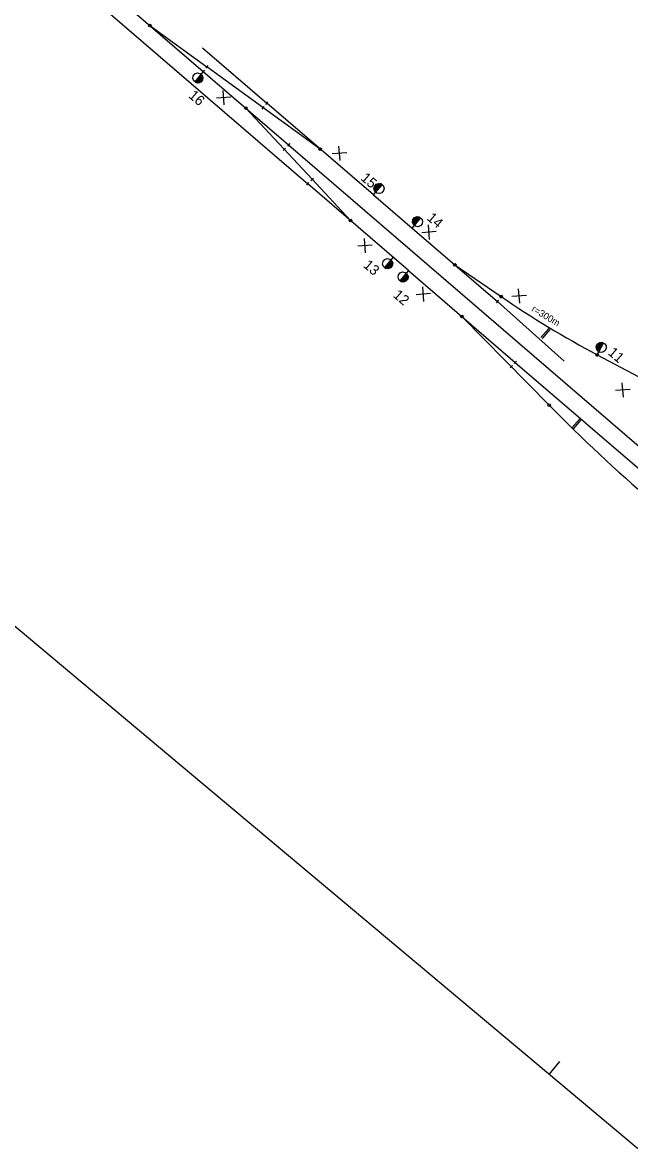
# Model space of a CAD drawing. Extents: x -473608 to -471381, y -1324122 to -1322275.
# Drawn here: x -473120 to -472940.5, y -1323062.2 to -1322731.6 of the extents above; entities that cross this region are included whole.
import ezdxf

# ---------------------------------------------------------------- set-up
doc = ezdxf.new("R2010")
doc.units = 0
for name, color, linetype in [('Level 1', 7, 'Continuous'), ('Level 10', 7, 'Continuous'), ('Level 11', 7, 'Continuous'), ('Level 61', 7, 'Continuous')]:
    doc.layers.add(name, color=color, linetype=linetype)

msp = doc.modelspace()

# ---------------------------------------------------------------- linework, layer by layer
at = {"layer": 'Level 1'}
for p, q in [((-473117.89, -1322708.6), (-473035.77, -1322779.3)), ((-473109.51, -1322709.21), (-473066.62, -1322746.14)), ((-473082.39, -1322732.57), (-473082.39, -1322732.57)), ((-473082.39, -1322732.57), (-473065.55, -1322744.78)), ((-473066.82, -1322739.17), (-473047.87, -1322755.48)), ((-473065.26, -1322744.38), (-473065.85, -1322745.19)), ((-473032.11, -1322769.05), (-473065.55, -1322744.78)), ((-473065.55, -1322744.78), (-473065.55, -1322744.78)), ((-473066.3, -1322745.76), (-473066.95, -1322746.52)), ((-473066.62, -1322746.14), (-473066.62, -1322746.14)), ((-473066.62, -1322746.14), (-473041.44, -1322767.82)), ((-473048.2, -1322755.86), (-473047.54, -1322755.1)), ((-473054.03, -1322756.98), (-473054.03, -1322756.98)), ((-473054.03, -1322756.98), (-473034.49, -1322777.98)), ((-473049.23, -1322757.24), (-473048.65, -1322756.43)), ((-473048.94, -1322756.83), (-473048.94, -1322756.83)), ((-473016.35, -1322782.61), (-473047.87, -1322755.48)), ((-473047.87, -1322755.48), (-473047.87, -1322755.48)), ((-473041.11, -1322767.44), (-473041.77, -1322768.2)), ((-473041.44, -1322767.82), (-473041.44, -1322767.82)), ((-473041.44, -1322767.82), (-472684.71, -1323074.94)), ((-473042.35, -1322768.8), (-473043.08, -1322769.49)), ((-473042.35, -1322768.8), (-473043.08, -1322769.49)), ((-473042.71, -1322769.14), (-473042.71, -1322769.14)), ((-473042.71, -1322769.14), (-473042.71, -1322769.14)), ((-473032.11, -1322769.05), (-473032.11, -1322769.05)), ((-473034.86, -1322778.32), (-473034.13, -1322777.64)), ((-473034.86, -1322778.32), (-473034.13, -1322777.64)), ((-473023.17, -1322790.15), (-473034.49, -1322777.98)), ((-473034.49, -1322777.98), (-473034.49, -1322777.98)), ((-473034.49, -1322777.98), (-473034.49, -1322777.98)), ((-473036.09, -1322779.68), (-473035.44, -1322778.93)), ((-473006.04, -1322804.9), (-473035.77, -1322779.3)), ((-473035.77, -1322779.3), (-473035.77, -1322779.3)), ((-473016.35, -1322782.61), (-473004.98, -1322792.4)), ((-473023.17, -1322790.15), (-473023.17, -1322790.15)), ((-473004.98, -1322792.4), (-472979.8, -1322814.08)), ((-473006.04, -1322804.9), (-472974.51, -1322832.04)), ((-472992.39, -1322803.24), (-472992.39, -1322803.24)), ((-472992.39, -1322803.24), (-472978.67, -1322812.63)), ((-472979.47, -1322813.71), (-472980.12, -1322814.46)), ((-472979.8, -1322814.08), (-472979.8, -1322814.08)), ((-472979.8, -1322814.08), (-472960.11, -1322831.67)), ((-472978.4, -1322812.22), (-472978.96, -1322813.04)), ((-472978.68, -1322812.63), (-472978.68, -1322812.63)), ((-472978.67, -1322812.63), (-472978.67, -1322812.63)), ((-472990.28, -1322818.47), (-472990.28, -1322818.47)), ((-472990.28, -1322818.47), (-472964.54, -1322844.65)), ((-472950.3, -1322829.82), (-472950.3, -1322829.82)), ((-472950.3, -1322829.82), (-472920.97, -1322845.45)), ((-472950.3, -1322829.82), (-472950.3, -1322829.82)), ((-472975.34, -1322832.95), (-472976.05, -1322833.65)), ((-472975.7, -1322833.3), (-472975.7, -1322833.3)), ((-472974.19, -1322831.66), (-472974.84, -1322832.42)), ((-472974.51, -1322832.04), (-472974.51, -1322832.04)), ((-472974.51, -1322832.04), (-472688.76, -1323078.05)), ((-472964.54, -1322844.65), (-472964.54, -1322844.65))]:
    msp.add_line(p, q, dxfattribs=at)
for points in [[(-473082.08, -1322732.83), (-473082.46, -1322732.96), (-473082.76, -1322732.7), (-473082.69, -1322732.31), (-473082.31, -1322732.18), (-473082.01, -1322732.44), (-473082.08, -1322732.83)], [(-473053.73, -1322757.24), (-473054.1, -1322757.37), (-473054.41, -1322757.11), (-473054.34, -1322756.72), (-473053.96, -1322756.59), (-473053.65, -1322756.85), (-473053.73, -1322757.24)], [(-473032.41, -1322768.79), (-473032.04, -1322768.65), (-473031.73, -1322768.91), (-473031.81, -1322769.31), (-473032.18, -1322769.44), (-473032.49, -1322769.18), (-473032.41, -1322768.79)], [(-473023.48, -1322789.88), (-473023.1, -1322789.75), (-473022.8, -1322790.01), (-473022.87, -1322790.41), (-473023.25, -1322790.54), (-473023.55, -1322790.28), (-473023.48, -1322789.88)], [(-472992.09, -1322803.5), (-472992.46, -1322803.64), (-472992.76, -1322803.38), (-472992.69, -1322802.98), (-472992.31, -1322802.85), (-472992.01, -1322803.11), (-472992.09, -1322803.5)], [(-472978.44, -1322812.3), (-472978.27, -1322812.66), (-472978.5, -1322812.99), (-472978.89, -1322812.96), (-472979.07, -1322812.6), (-472978.84, -1322812.27), (-472978.44, -1322812.3)], [(-472989.97, -1322818.73), (-472990.35, -1322818.86), (-472990.65, -1322818.6), (-472990.58, -1322818.21), (-472990.2, -1322818.08), (-472989.9, -1322818.34), (-472989.97, -1322818.73)], [(-472950.49, -1322830.18), (-472950.7, -1322829.84), (-472950.51, -1322829.49), (-472950.11, -1322829.47), (-472949.9, -1322829.81), (-472950.09, -1322830.16), (-472950.49, -1322830.18)], [(-472964.26, -1322844.36), (-472964.16, -1322844.75), (-472964.45, -1322845.03), (-472964.83, -1322844.93), (-472964.93, -1322844.54), (-472964.65, -1322844.26), (-472964.26, -1322844.36)]]:
    msp.add_lwpolyline(points, dxfattribs=at)
for centre, radius, start, end in [((-472809.24, -1322565.05), 300, 235.6149, 241.9536), ((-472607.98, -1322494.12), 500, 224.5106, 229.2718)]:
    msp.add_arc(centre, radius, start, end, dxfattribs=at)
at = {"layer": 'Level 10'}
for p, q in [((-472964.65, -1322822.02), (-472966.93, -1322824.68)), ((-472964.3, -1322822.32), (-472966.58, -1322824.97)), ((-472955.5, -1322848.72), (-472957.78, -1322851.37)), ((-472955.15, -1322849.01), (-472957.43, -1322851.67))]:
    msp.add_line(p, q, dxfattribs=at)
at = {"layer": 'Level 11'}
for p, q in [((-473066.62, -1322746.14), (-473069.16, -1322749.16)), ((-473066.62, -1322746.14), (-473066.62, -1322746.14)), ((-473060.47, -1322756.03), (-473060.79, -1322751.76)), ((-473058.5, -1322753.73), (-473062.77, -1322754.05)), ((-473026.25, -1322772.42), (-473026.57, -1322768.16)), ((-473024.28, -1322770.13), (-473028.54, -1322770.45)), ((-473016.35, -1322782.61), (-473013.81, -1322779.59)), ((-473016.35, -1322782.61), (-473016.35, -1322782.61)), ((-473004.98, -1322792.4), (-473002.44, -1322789.38)), ((-472999.86, -1322795.71), (-473000.18, -1322791.44)), ((-473004.98, -1322792.4), (-473004.98, -1322792.4)), ((-472997.89, -1322793.42), (-473002.15, -1322793.74)), ((-473016.72, -1322797.41), (-473020.98, -1322797.73)), ((-473018.69, -1322799.7), (-473019.01, -1322795.44)), ((-473010.58, -1322800.99), (-473013.12, -1322804.01)), ((-473010.58, -1322800.99), (-473010.58, -1322800.99)), ((-473006.04, -1322804.9), (-473008.57, -1322807.93)), ((-473006.04, -1322804.9), (-473006.04, -1322804.9)), ((-473001.51, -1322814.03), (-473001.83, -1322809.77)), ((-472973.2, -1322814.58), (-472973.52, -1322810.32)), ((-472999.54, -1322811.74), (-473003.8, -1322812.06)), ((-472971.22, -1322812.29), (-472975.49, -1322812.61)), ((-472950.3, -1322829.82), (-472948.44, -1322826.34)), ((-472950.3, -1322829.82), (-472950.3, -1322829.82)), ((-472940.61, -1322840.04), (-472944.88, -1322840.36)), ((-472942.59, -1322842.33), (-472942.91, -1322838.07))]:
    msp.add_line(p, q, dxfattribs=at)
for points in [[(-473068.86, -1322749.42), (-473069.47, -1322748.91), (-473069.73, -1322748.16), (-473069.6, -1322747.43), (-473069.09, -1322746.81), (-473068.36, -1322746.56), (-473067.6, -1322746.69), (-473066.99, -1322747.2), (-473066.74, -1322747.92), (-473066.87, -1322748.69), (-473067.37, -1322749.28), (-473068.1, -1322749.55), (-473068.86, -1322749.42), (-473068.5, -1322749.39), (-473068.89, -1322749.07), (-473068.7, -1322748.84), (-473068.04, -1322749.39), (-473067.74, -1322749.25), (-473068.5, -1322748.61), (-473068.31, -1322748.38), (-473067.43, -1322749.12), (-473067.23, -1322748.89), (-473068.12, -1322748.15), (-473067.92, -1322747.92), (-473067.04, -1322748.66), (-473066.96, -1322748.33), (-473067.73, -1322747.69), (-473067.54, -1322747.46), (-473066.92, -1322747.97), (-473067, -1322747.52), (-473067.35, -1322747.23)], [(-473014.11, -1322779.33), (-473013.5, -1322779.85), (-473013.24, -1322780.59), (-473013.38, -1322781.33), (-473013.88, -1322781.93), (-473014.61, -1322782.2), (-473015.37, -1322782.07), (-473015.98, -1322781.55), (-473016.24, -1322780.83), (-473016.11, -1322780.07), (-473015.6, -1322779.46), (-473014.87, -1322779.21), (-473014.11, -1322779.33), (-473014.47, -1322779.36), (-473014.09, -1322779.68), (-473014.28, -1322779.91), (-473014.93, -1322779.37), (-473015.28, -1322779.47), (-473014.47, -1322780.14), (-473014.66, -1322780.37), (-473015.54, -1322779.63), (-473015.74, -1322779.86), (-473014.86, -1322780.6), (-473015.05, -1322780.83), (-473015.93, -1322780.09), (-473016.01, -1322780.42), (-473015.24, -1322781.06), (-473015.43, -1322781.29), (-473016.09, -1322780.75), (-473016.01, -1322781.2), (-473015.63, -1322781.52)], [(-473002.75, -1322789.12), (-473002.14, -1322789.63), (-473001.88, -1322790.38), (-473002.02, -1322791.12), (-473002.51, -1322791.72), (-473003.24, -1322791.98), (-473004, -1322791.85), (-473004.61, -1322791.34), (-473004.87, -1322790.62), (-473004.74, -1322789.86), (-473004.23, -1322789.25), (-473003.51, -1322788.99), (-473002.75, -1322789.12), (-473003.1, -1322789.15), (-473002.72, -1322789.47), (-473002.91, -1322789.7), (-473003.56, -1322789.16), (-473003.91, -1322789.26), (-473003.1, -1322789.93), (-473003.3, -1322790.16), (-473004.18, -1322789.42), (-473004.37, -1322789.65), (-473003.49, -1322790.39), (-473003.68, -1322790.62), (-473004.56, -1322789.88), (-473004.64, -1322790.21), (-473003.88, -1322790.85), (-473004.07, -1322791.08), (-473004.72, -1322790.53), (-473004.64, -1322790.99), (-473004.26, -1322791.31)], [(-473012.82, -1322804.27), (-473013.43, -1322803.76), (-473013.68, -1322803.01), (-473013.56, -1322802.28), (-473013.04, -1322801.66), (-473012.32, -1322801.41), (-473011.56, -1322801.53), (-473010.95, -1322802.05), (-473010.69, -1322802.77), (-473010.83, -1322803.53), (-473011.33, -1322804.13), (-473012.06, -1322804.4), (-473012.82, -1322804.27), (-473012.46, -1322804.24), (-473012.85, -1322803.92), (-473012.65, -1322803.69), (-473012, -1322804.23), (-473011.69, -1322804.1), (-473012.46, -1322803.46), (-473012.27, -1322803.23), (-473011.39, -1322803.97), (-473011.19, -1322803.74), (-473012.07, -1322803), (-473011.88, -1322802.77), (-473011, -1322803.51), (-473010.92, -1322803.18), (-473011.69, -1322802.54), (-473011.5, -1322802.31), (-473010.88, -1322802.82), (-473010.96, -1322802.37), (-473011.3, -1322802.08)], [(-473008.27, -1322808.18), (-473008.88, -1322807.67), (-473009.14, -1322806.92), (-473009.01, -1322806.19), (-473008.5, -1322805.58), (-473007.77, -1322805.32), (-473007.02, -1322805.45), (-473006.4, -1322805.96), (-473006.15, -1322806.69), (-473006.28, -1322807.45), (-473006.78, -1322808.04), (-473007.51, -1322808.31), (-473008.27, -1322808.18), (-473007.92, -1322808.15), (-473008.3, -1322807.83), (-473008.11, -1322807.6), (-473007.45, -1322808.15), (-473007.15, -1322808.02), (-473007.91, -1322807.37), (-473007.72, -1322807.14), (-473006.84, -1322807.88), (-473006.65, -1322807.65), (-473007.53, -1322806.91), (-473007.33, -1322806.68), (-473006.45, -1322807.42), (-473006.38, -1322807.1), (-473007.14, -1322806.45), (-473006.95, -1322806.22), (-473006.34, -1322806.74), (-473006.41, -1322806.28), (-473006.76, -1322805.99)], [(-472948.79, -1322826.15), (-472948.09, -1322826.53), (-472947.68, -1322827.2), (-472947.66, -1322827.95), (-472948.03, -1322828.65), (-472948.69, -1322829.05), (-472949.45, -1322829.08), (-472950.16, -1322828.71), (-472950.56, -1322828.05), (-472950.59, -1322827.28), (-472950.22, -1322826.59), (-472949.56, -1322826.18), (-472948.79, -1322826.15), (-472949.13, -1322826.25), (-472948.69, -1322826.49), (-472948.83, -1322826.75), (-472949.58, -1322826.35), (-472949.86, -1322826.55), (-472948.97, -1322827.02), (-472949.11, -1322827.28), (-472950.13, -1322826.74), (-472950.27, -1322827.01), (-472949.26, -1322827.55), (-472949.4, -1322827.81), (-472950.41, -1322827.27), (-472950.42, -1322827.6), (-472949.54, -1322828.08), (-472949.68, -1322828.34), (-472950.39, -1322827.96), (-472950.22, -1322828.39), (-472949.82, -1322828.6)]]:
    msp.add_lwpolyline(points, dxfattribs=at)
at = {"layer": 'Level 61'}
for p, q in [((-472803.67, -1323177.35), (-473608.02, -1322502.42)), ((-472964.54, -1323042.36), (-472961.33, -1323038.53))]:
    msp.add_line(p, q, dxfattribs=at)

# ---------------------------------------------------------------- texts
at = {"layer": 'Level 10'}
msp.add_text('r=300m', height=2, rotation=329.0639, dxfattribs=at).set_placement((-472969.9, -1322816.81))
at = {"layer": 'Level 11'}
for s, p in [('16', (-473071.21, -1322753.6)), ('15', (-473020.35, -1322777.95)), ('14', (-473000.84, -1322789.73)), ('13', (-473019.6, -1322803.69)), ('12', (-473010.8, -1322812.52)), ('11', (-472947.36, -1322829.51))]:
    msp.add_text(s, height=3, rotation=319.3, dxfattribs=at).set_placement(p)

doc.saveas('drawing.dxf')
